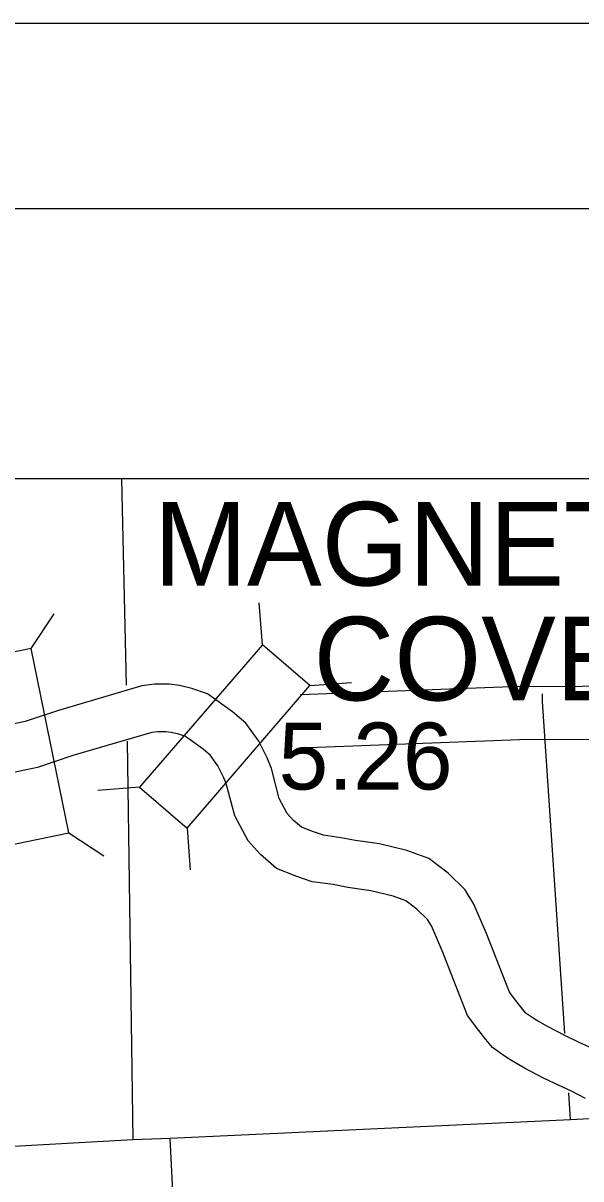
# Model space of a CAD drawing. Extents: x 22866 to 28196, y 1324810 to 1328105.
# Drawn here: x 24310.9 to 24428, y 1327299.2 to 1327541.9 of the extents above; entities that cross this region are included whole.
import ezdxf

# ---------------------------------------------------------------- set-up
doc = ezdxf.new("R2010")
doc.units = 0
for name, color, linetype in [('Level 15', 7, 'Continuous'), ('Level 20', 7, 'Continuous'), ('Level 4', 7, 'Continuous'), ('Level 5', 7, 'Continuous'), ('Level 58', 7, 'Continuous'), ('Level 6', 7, 'Continuous'), ('R_Border', 7, 'Continuous'), ('R_No Plot', 7, 'Continuous')]:
    doc.layers.add(name, color=color, linetype=linetype)

msp = doc.modelspace()

# ---------------------------------------------------------------- linework, layer by layer
at = {"layer": 'Level 15'}
for points in [[(24430.42, 1327326.6), (24427.67, 1327327.86), (24424.62, 1327329.32), (24421.16, 1327331.13), (24418.78, 1327332.51), (24417.75, 1327333.15), (24416.53, 1327333.97), (24416.36, 1327334.1), (24415.79, 1327334.77), (24414.54, 1327336.41), (24413.03, 1327338.44), (24408.21, 1327350.75), (24405.52, 1327356.95), (24403.7, 1327359.93), (24400.13, 1327363.45), (24396.09, 1327366.51), (24391.45, 1327368.2), (24385.73, 1327369.55), (24380.72, 1327370.27), (24377.64, 1327370.86), (24373.96, 1327371.37), (24371.85, 1327372.1), (24369.32, 1327373.1), (24367.69, 1327374.48), (24366.37, 1327375.96), (24364.69, 1327379.11), (24363.05, 1327385.43), (24362.13, 1327387.63), (24360.36, 1327391.14), (24357.65, 1327394.91), (24354.86, 1327397.31), (24349.62, 1327401.08), (24346.36, 1327402.21), (24343.77, 1327402.8), (24341.59, 1327403.1), (24338.46, 1327403.1), (24335.83, 1327402.76), (24318.32, 1327397.61), (24311.34, 1327395.26), (24307.01, 1327394.37)], [(24430.42, 1327326.6), (24427.67, 1327327.86), (24424.62, 1327329.32), (24421.16, 1327331.13), (24418.78, 1327332.51), (24417.75, 1327333.15), (24416.53, 1327333.97), (24416.36, 1327334.1), (24415.79, 1327334.77), (24414.54, 1327336.41), (24413.03, 1327338.44), (24408.21, 1327350.75), (24405.52, 1327356.95), (24403.7, 1327359.93), (24400.13, 1327363.45), (24396.09, 1327366.51), (24391.45, 1327368.2), (24385.73, 1327369.55), (24380.72, 1327370.27), (24377.64, 1327370.86), (24373.96, 1327371.37), (24371.85, 1327372.1), (24369.32, 1327373.1), (24367.69, 1327374.48), (24366.37, 1327375.96), (24364.69, 1327379.11), (24363.05, 1327385.43), (24362.13, 1327387.63), (24360.36, 1327391.14), (24357.65, 1327394.91), (24354.86, 1327397.31), (24349.62, 1327401.08), (24346.36, 1327402.21), (24343.77, 1327402.8), (24341.59, 1327403.1), (24338.46, 1327403.1), (24335.83, 1327402.76), (24318.32, 1327397.61), (24311.34, 1327395.26), (24307.01, 1327394.37)], [(24428.98, 1327316.13), (24426.07, 1327317.63), (24423.44, 1327318.83), (24420.15, 1327320.4), (24416.34, 1327322.39), (24413.65, 1327323.95), (24412.32, 1327324.78), (24410.69, 1327325.88), (24409.44, 1327326.84), (24408.02, 1327328.52), (24406.58, 1327330.41), (24404.23, 1327333.54), (24398.99, 1327346.95), (24396.65, 1327352.34), (24395.83, 1327353.69), (24393.6, 1327355.88), (24391.26, 1327357.65), (24388.59, 1327358.63), (24383.88, 1327359.74), (24379.08, 1327360.43), (24376.02, 1327361.01), (24371.62, 1327361.62), (24368.38, 1327362.75), (24364.12, 1327364.43), (24360.72, 1327367.32), (24358.13, 1327370.2), (24355.33, 1327375.46), (24353.57, 1327382.25), (24353.06, 1327383.47), (24351.81, 1327385.95), (24350.24, 1327388.12), (24348.68, 1327389.47), (24344.98, 1327392.13), (24343.61, 1327392.61), (24341.99, 1327392.98), (24340.9, 1327393.12), (24339.11, 1327393.13), (24337.9, 1327392.97), (24321.32, 1327388.1), (24313.95, 1327385.61), (24308.57, 1327384.51)], [(24428.98, 1327316.13), (24426.07, 1327317.63), (24423.44, 1327318.83), (24420.15, 1327320.4), (24416.34, 1327322.39), (24413.65, 1327323.95), (24412.32, 1327324.78), (24410.69, 1327325.88), (24409.44, 1327326.84), (24408.02, 1327328.52), (24406.58, 1327330.41), (24404.23, 1327333.54), (24398.99, 1327346.95), (24396.65, 1327352.34), (24395.83, 1327353.69), (24393.6, 1327355.88), (24391.26, 1327357.65), (24388.59, 1327358.63), (24383.88, 1327359.74), (24379.08, 1327360.43), (24376.02, 1327361.01), (24371.62, 1327361.62), (24368.38, 1327362.75), (24364.12, 1327364.43), (24360.72, 1327367.32), (24358.13, 1327370.2), (24355.33, 1327375.46), (24353.57, 1327382.25), (24353.06, 1327383.47), (24351.81, 1327385.95), (24350.24, 1327388.12), (24348.68, 1327389.47), (24344.98, 1327392.13), (24343.61, 1327392.61), (24341.99, 1327392.98), (24340.9, 1327393.12), (24339.11, 1327393.13), (24337.9, 1327392.97), (24321.32, 1327388.1), (24313.95, 1327385.61), (24308.57, 1327384.51)]]:
    msp.add_lwpolyline(points, dxfattribs=at)
at = {"layer": 'Level 20'}
for p, q in [((24361.13, 1327411.39), (24360.48, 1327420.15)), ((24361.13, 1327411.39), (24360.48, 1327420.15)), ((24312.58, 1327410.58), (24317.42, 1327417.9)), ((24312.58, 1327410.58), (24317.42, 1327417.9)), ((24371.11, 1327402.8), (24379.86, 1327403.45)), ((24371.11, 1327402.8), (24379.86, 1327403.45)), ((24335.35, 1327381.47), (24326.6, 1327380.81)), ((24335.35, 1327381.47), (24326.6, 1327380.81)), ((24320.5, 1327371.88), (24327.82, 1327367.04)), ((24320.5, 1327371.88), (24327.82, 1327367.04)), ((24345.33, 1327372.87), (24345.98, 1327364.12)), ((24345.33, 1327372.87), (24345.98, 1327364.12))]:
    msp.add_line(p, q, dxfattribs=at)
for points in [[(24299.68, 1327407.94), (24307.6, 1327369.24), (24320.5, 1327371.88), (24312.58, 1327410.58)], [(24299.68, 1327407.94), (24307.6, 1327369.24), (24320.5, 1327371.88), (24312.58, 1327410.58)], [(24361.13, 1327411.39), (24335.35, 1327381.47), (24345.33, 1327372.87), (24371.11, 1327402.8)], [(24361.13, 1327411.39), (24335.35, 1327381.47), (24345.33, 1327372.87), (24371.11, 1327402.8)]]:
    msp.add_lwpolyline(points, close=True, dxfattribs=at)
at = {"layer": 'Level 4'}
msp.add_lwpolyline([(24436.45, 1327312.14), (24433.83, 1327312.04), (24425.83, 1327311.63), (24341.78, 1327307.69), (24333.92, 1327307.41), (24305.09, 1327305.86)], dxfattribs=at)
msp.add_lwpolyline([(24436.45, 1327312.14), (24433.83, 1327312.04), (24425.83, 1327311.63), (24341.78, 1327307.69), (24333.92, 1327307.41), (24305.09, 1327305.86)], dxfattribs=at)
at = {"layer": 'Level 5'}
for points in [[(24331.54, 1327446.26), (24331.7, 1327439.9), (24332.54, 1327402.89)], [(24331.54, 1327446.26), (24331.7, 1327439.9), (24332.54, 1327402.89)], [(24487.98, 1327402.92), (24413.36, 1327402.55), (24369.17, 1327400.9)], [(24424.63, 1327329.75), (24419.98, 1327399.45), (24419.95, 1327401.06)], [(24424.63, 1327329.75), (24419.98, 1327399.45), (24419.95, 1327401.06)], [(24332.76, 1327391.17), (24333.92, 1327307.41)], [(24332.76, 1327391.17), (24333.92, 1327307.41)], [(24489.72, 1327391.79), (24415.1, 1327391.42), (24370.91, 1327389.77)], [(24425.83, 1327311.63), (24425.46, 1327317.28)], [(24425.83, 1327311.63), (24425.46, 1327317.28)], [(24345.18, 1327240.34), (24341.78, 1327307.69)], [(24345.18, 1327240.34), (24341.78, 1327307.69)]]:
    msp.add_lwpolyline(points, dxfattribs=at)
at = {"layer": 'R_Border'}
msp.add_line((23883.86, 1327502.95), (27045.59, 1327502.95), dxfattribs=at)
at = {"layer": 'R_No Plot'}
msp.add_line((23759.85, 1327541.9), (27093.11, 1327541.9), dxfattribs=at)
for points in [[(23759.79, 1327541.9), (27093.11, 1327541.9), (27093.11, 1325408.57), (23759.79, 1325408.57)], [(23932.69, 1327446.26), (24728.44, 1327446.26), (24728.44, 1326652.92), (23932.69, 1326652.92)]]:
    msp.add_lwpolyline(points, close=True, dxfattribs=at)

# ---------------------------------------------------------------- texts
at = {"layer": 'Level 58'}
msp.add_text('5.26', height=14.044, dxfattribs=at).set_placement((24364.53, 1327380.99))
msp.add_text('5.26', height=14.044, dxfattribs=at).set_placement((24364.53, 1327380.99))
at = {"layer": 'Level 6'}
for s, p in [('MAGNET', (24338.38, 1327423.81)), ('MAGNET', (24338.38, 1327423.81)), ('COVE', (24371.88, 1327399.7)), ('COVE', (24371.88, 1327399.7))]:
    msp.add_text(s, height=17.555, dxfattribs=at).set_placement(p)

doc.saveas('drawing.dxf')
